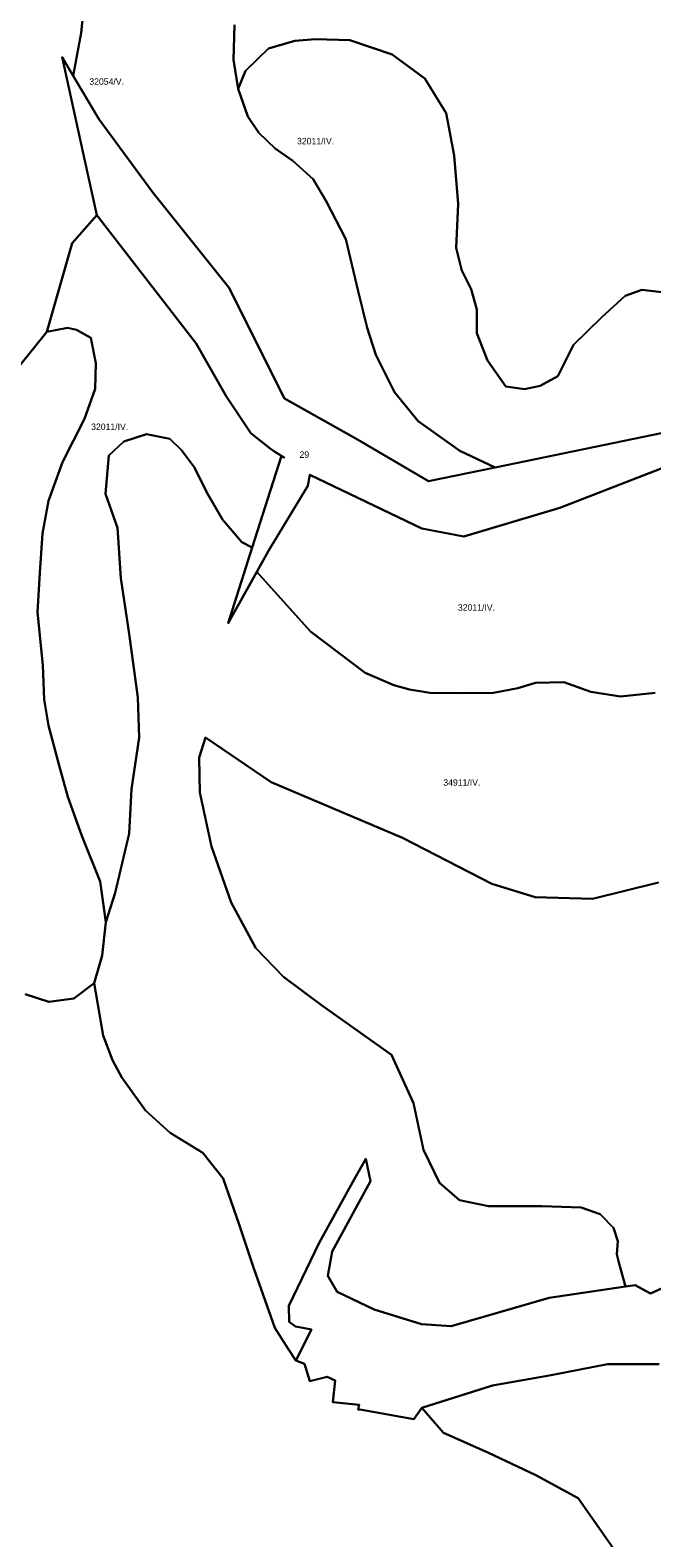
# Model space of a CAD drawing. Extents: x -521621 to -516761, y -1190184 to -1184927.
# Drawn here: x -518790 to -518405, y -1186934 to -1186003 of the extents above; entities that cross this region are included whole.
import ezdxf

# ---------------------------------------------------------------- set-up
doc = ezdxf.new("R2010")
doc.units = 0
doc.layers.add('BPEJ_s', color=7, linetype='Continuous')

msp = doc.modelspace()

# ---------------------------------------------------------------- linework, layer by layer
at = {"layer": 'BPEJ_s'}
for points in [[(-518755.34, -1185978.17), (-518758.01, -1186004.22), (-518762.89, -1186030.84), (-518769.77, -1186019.26), (-518758.59, -1186070.21), (-518748.37, -1186116.79), (-518763.55, -1186134.17), (-518779.14, -1186188.98), (-518803.71, -1186219.42)], [(-518663.33, -1185999.19), (-518663.92, -1186020.8), (-518660.96, -1186038.86), (-518655.06, -1186055.93), (-518648.33, -1186066.04), (-518638.23, -1186075.72), (-518627.28, -1186083.3), (-518614.66, -1186094.67), (-518606.66, -1186108.15), (-518594.46, -1186131.73), (-518586.88, -1186163.74), (-518581.41, -1186186.48), (-518576.05, -1186203.16), (-518564.51, -1186226.26), (-518549.71, -1186244.02), (-518523.97, -1186262.37), (-518502.28, -1186272.68), (-518543.48, -1186281.2), (-518587.23, -1186255.36), (-518632.34, -1186230.07), (-518666.87, -1186161.64), (-518713.8, -1186102.84), (-518746.89, -1186057.79), (-518762.89, -1186030.84), (-518758.01, -1186004.22), (-518755.34, -1185978.17)], [(-518390.45, -1186165.48), (-518411.54, -1186162.94), (-518421.91, -1186166.68), (-518436.64, -1186180.16), (-518453.89, -1186197), (-518463.57, -1186216.37), (-518474.51, -1186222.27), (-518484.19, -1186224.37), (-518495.56, -1186222.69), (-518506.92, -1186206.69), (-518513.65, -1186189.84), (-518513.65, -1186175.1), (-518517.02, -1186162.47), (-518522.91, -1186151.1), (-518526.28, -1186137.21), (-518525.02, -1186109.83), (-518527.54, -1186079.93), (-518532.59, -1186053.82), (-518545.64, -1186032.35), (-518565.84, -1186017.61), (-518591.93, -1186008.77), (-518613.33, -1186008.07), (-518626.05, -1186009.25), (-518642.32, -1186013.99), (-518656.52, -1186027.61), (-518660.96, -1186038.86), (-518663.92, -1186020.8), (-518663.33, -1185999.19)], [(-518398.58, -1186251.24), (-518502.28, -1186272.68), (-518523.97, -1186262.37), (-518549.71, -1186244.02), (-518564.51, -1186226.26), (-518576.05, -1186203.16), (-518581.41, -1186186.48), (-518586.88, -1186163.74), (-518594.46, -1186131.73), (-518606.66, -1186108.15), (-518614.66, -1186094.67), (-518627.28, -1186083.3), (-518638.23, -1186075.72), (-518648.33, -1186066.04), (-518655.06, -1186055.93), (-518660.96, -1186038.86), (-518656.52, -1186027.61), (-518642.32, -1186013.99), (-518626.05, -1186009.25), (-518613.33, -1186008.07), (-518591.93, -1186008.77), (-518565.84, -1186017.61), (-518545.64, -1186032.35), (-518532.59, -1186053.82), (-518527.54, -1186079.93), (-518525.02, -1186109.83), (-518526.28, -1186137.21), (-518522.91, -1186151.1), (-518517.02, -1186162.47), (-518513.65, -1186175.1), (-518513.65, -1186189.84), (-518506.92, -1186206.69), (-518495.56, -1186222.69), (-518484.19, -1186224.37), (-518474.51, -1186222.27), (-518463.57, -1186216.37), (-518453.89, -1186197), (-518436.64, -1186180.16), (-518421.91, -1186166.68), (-518411.54, -1186162.94), (-518390.45, -1186165.48)], [(-518373.06, -1186263.06), (-518462.29, -1186297.62), (-518521.64, -1186315.37), (-518547.55, -1186310.37), (-518616.73, -1186277.29), (-518618.04, -1186284.1), (-518642.2, -1186324.24), (-518649.43, -1186337.23), (-518667.13, -1186369), (-518652.28, -1186322.17), (-518634.49, -1186266.09), (-518632.69, -1186266.61), (-518638.34, -1186263), (-518641.17, -1186260.95), (-518653.25, -1186251.43), (-518668.53, -1186228.68), (-518686.91, -1186196.11), (-518748.37, -1186116.79), (-518758.59, -1186070.21), (-518769.77, -1186019.26), (-518762.89, -1186030.84), (-518746.89, -1186057.79), (-518713.8, -1186102.84), (-518666.87, -1186161.64), (-518632.34, -1186230.07), (-518587.23, -1186255.36), (-518543.48, -1186281.2), (-518502.28, -1186272.68), (-518398.58, -1186251.24)], [(-518803.71, -1186219.42), (-518779.14, -1186188.98), (-518766.43, -1186186.47), (-518760.84, -1186187.71), (-518752.15, -1186192.68), (-518748.95, -1186208.37), (-518749.28, -1186224.04), (-518755.95, -1186242.72), (-518769.61, -1186269.4), (-518778.28, -1186293.41), (-518781.94, -1186313.42), (-518783.61, -1186337.76), (-518784.94, -1186362.11), (-518781.61, -1186394.79), (-518780.94, -1186416.14), (-518778.28, -1186432.14), (-518771.61, -1186456.82), (-518766.28, -1186476.17), (-518757.6, -1186500.24), (-518746.34, -1186528.56), (-518742.69, -1186553.54), (-518745.12, -1186574.25), (-518749.99, -1186591.3), (-518762.47, -1186600.74), (-518778, -1186602.88), (-518792.61, -1186598)], [(-518401.39, -1186529.05), (-518442.01, -1186539.22), (-518477.56, -1186538.26), (-518504.22, -1186530.01), (-518559.44, -1186501.43), (-518640.68, -1186467.13), (-518681.31, -1186439.5), (-518685.12, -1186451.89), (-518684.8, -1186473.48), (-518677.5, -1186506.82), (-518665.44, -1186541.44), (-518650.2, -1186569.7), (-518633.07, -1186587.49), (-518609.61, -1186604.89), (-518566.31, -1186635.58), (-518552.78, -1186665.36), (-518546.47, -1186694.24), (-518536.54, -1186714.55), (-518524.37, -1186725.38), (-518506.33, -1186728.99), (-518473.4, -1186728.99), (-518449.05, -1186729.9), (-518437.32, -1186733.96), (-518429.2, -1186742.53), (-518426.5, -1186750.66), (-518427.02, -1186758.62), (-518425.83, -1186763.8), (-518421.78, -1186778.73), (-518468.84, -1186785.74), (-518498.81, -1186794.43), (-518529.34, -1186803.13), (-518547.69, -1186802.01), (-518576.96, -1186792.89), (-518599.8, -1186782.01), (-518605.57, -1186772.17), (-518603.01, -1186756.98), (-518579.29, -1186713.55), (-518582.06, -1186699.86), (-518589.12, -1186712.27), (-518610.91, -1186751.63), (-518629.72, -1186790.56), (-518629.47, -1186800.57), (-518625.56, -1186803.41), (-518620.98, -1186804.32), (-518615.73, -1186805.32), (-518625.42, -1186824.4), (-518630.19, -1186817.27), (-518638.37, -1186804.29), (-518651.63, -1186767.02), (-518660.38, -1186740.48), (-518670.25, -1186711.96), (-518682.95, -1186696.15), (-518702.98, -1186683.73), (-518718.22, -1186669.9), (-518732.89, -1186649.57), (-518738.73, -1186638.81), (-518744.51, -1186623.59), (-518749.99, -1186591.3), (-518745.12, -1186574.25), (-518742.69, -1186553.54), (-518736.95, -1186535.53), (-518728.28, -1186498.84), (-518726.95, -1186471.5), (-518722.28, -1186439.48), (-518722.95, -1186414.8), (-518728.28, -1186375.45), (-518733.62, -1186341.1), (-518735.62, -1186310.08), (-518742.95, -1186289.07), (-518740.95, -1186265.4), (-518731.62, -1186256.73), (-518717.62, -1186252.06), (-518703.29, -1186255.06), (-518695.95, -1186262.06), (-518687.96, -1186272.73), (-518680.29, -1186288.27), (-518670.73, -1186304.88), (-518658.79, -1186318.79), (-518652.28, -1186322.17), (-518667.13, -1186369), (-518649.43, -1186337.23), (-518616.27, -1186374.14), (-518582.58, -1186399.67), (-518564.92, -1186407.2), (-518555.21, -1186409.96), (-518542.56, -1186411.92), (-518524.29, -1186412.21), (-518503.2, -1186411.92), (-518488.3, -1186409.11), (-518477.33, -1186405.74), (-518459.9, -1186405.45), (-518443.03, -1186411.36), (-518424.75, -1186414.18), (-518403.38, -1186411.93)], [(-518403.38, -1186411.93), (-518424.75, -1186414.18), (-518443.03, -1186411.36), (-518459.9, -1186405.45), (-518477.33, -1186405.74), (-518488.3, -1186409.11), (-518503.2, -1186411.92), (-518524.29, -1186412.21), (-518542.56, -1186411.92), (-518555.21, -1186409.96), (-518564.92, -1186407.2), (-518582.58, -1186399.67), (-518616.27, -1186374.14), (-518649.43, -1186337.23), (-518642.2, -1186324.24), (-518618.04, -1186284.1), (-518616.73, -1186277.29), (-518547.55, -1186310.37), (-518521.64, -1186315.37), (-518462.29, -1186297.62), (-518373.06, -1186263.06)], [(-518381.71, -1186771.88), (-518406.33, -1186783.1), (-518415.68, -1186777.9), (-518421.78, -1186778.73), (-518425.83, -1186763.8), (-518427.02, -1186758.62), (-518426.5, -1186750.66), (-518429.2, -1186742.53), (-518437.32, -1186733.96), (-518449.05, -1186729.9), (-518473.4, -1186728.99), (-518506.33, -1186728.99), (-518524.37, -1186725.38), (-518536.54, -1186714.55), (-518546.47, -1186694.24), (-518552.78, -1186665.36), (-518566.31, -1186635.58), (-518609.61, -1186604.89), (-518633.07, -1186587.49), (-518650.2, -1186569.7), (-518665.44, -1186541.44), (-518677.5, -1186506.82), (-518684.8, -1186473.48), (-518685.12, -1186451.89), (-518681.31, -1186439.5), (-518640.68, -1186467.13), (-518559.44, -1186501.43), (-518504.22, -1186530.01), (-518477.56, -1186538.26), (-518442.01, -1186539.22), (-518401.39, -1186529.05)], [(-518792.61, -1186598), (-518778, -1186602.88), (-518762.47, -1186600.74), (-518749.99, -1186591.3), (-518744.51, -1186623.59), (-518738.73, -1186638.81), (-518732.89, -1186649.57), (-518718.22, -1186669.9), (-518702.98, -1186683.73), (-518682.95, -1186696.15), (-518670.25, -1186711.96), (-518660.38, -1186740.48), (-518651.63, -1186767.02), (-518638.37, -1186804.29), (-518630.19, -1186817.27), (-518625.42, -1186824.4), (-518620.06, -1186826.43), (-518616.73, -1186837.25), (-518606.01, -1186834.51), (-518601.12, -1186836.85), (-518601.71, -1186842.53), (-518602.52, -1186850.05), (-518586.36, -1186851.87), (-518586.88, -1186854.75), (-518584.71, -1186854.82), (-518552.44, -1186860.72), (-518547.6, -1186853.6), (-518534.23, -1186869.07), (-518506.69, -1186881.17), (-518477.12, -1186895.29), (-518450.92, -1186909.41), (-518429.42, -1186940.33)], [(-518400.97, -1186826.76), (-518432.75, -1186826.64), (-518467.55, -1186833.37), (-518503.82, -1186839.81), (-518547.6, -1186853.6), (-518552.44, -1186860.72), (-518584.71, -1186854.82), (-518586.88, -1186854.75), (-518586.36, -1186851.87), (-518602.52, -1186850.05), (-518601.71, -1186842.53), (-518601.12, -1186836.85), (-518606.01, -1186834.51), (-518616.73, -1186837.25), (-518620.06, -1186826.43), (-518625.42, -1186824.4), (-518615.73, -1186805.32), (-518620.98, -1186804.32), (-518625.56, -1186803.41), (-518629.47, -1186800.57), (-518629.72, -1186790.56), (-518610.91, -1186751.63), (-518589.12, -1186712.27), (-518582.06, -1186699.86), (-518579.29, -1186713.55), (-518603.01, -1186756.98), (-518605.57, -1186772.17), (-518599.8, -1186782.01), (-518576.96, -1186792.89), (-518547.69, -1186802.01), (-518529.34, -1186803.13), (-518498.81, -1186794.43), (-518468.84, -1186785.74), (-518421.78, -1186778.73), (-518415.68, -1186777.9), (-518406.33, -1186783.1), (-518381.71, -1186771.88)], [(-518429.42, -1186940.33), (-518450.92, -1186909.41), (-518477.12, -1186895.29), (-518506.69, -1186881.17), (-518534.23, -1186869.07), (-518547.6, -1186853.6), (-518503.82, -1186839.81), (-518467.55, -1186833.37), (-518432.75, -1186826.64), (-518400.97, -1186826.76)]]:
    msp.add_lwpolyline(points, dxfattribs=at)
msp.add_lwpolyline([(-518779.14, -1186188.98), (-518763.55, -1186134.17), (-518748.37, -1186116.79), (-518686.91, -1186196.11), (-518668.53, -1186228.68), (-518653.25, -1186251.43), (-518641.17, -1186260.95), (-518638.34, -1186263), (-518632.69, -1186266.61), (-518634.49, -1186266.09), (-518652.28, -1186322.17), (-518658.79, -1186318.79), (-518670.73, -1186304.88), (-518680.29, -1186288.27), (-518687.96, -1186272.73), (-518695.95, -1186262.06), (-518703.29, -1186255.06), (-518717.62, -1186252.06), (-518731.62, -1186256.73), (-518740.95, -1186265.4), (-518742.95, -1186289.07), (-518735.62, -1186310.08), (-518733.62, -1186341.1), (-518728.28, -1186375.45), (-518722.95, -1186414.8), (-518722.28, -1186439.48), (-518726.95, -1186471.5), (-518728.28, -1186498.84), (-518736.95, -1186535.53), (-518742.69, -1186553.54), (-518746.34, -1186528.56), (-518757.6, -1186500.24), (-518766.28, -1186476.17), (-518771.61, -1186456.82), (-518778.28, -1186432.14), (-518780.94, -1186416.14), (-518781.61, -1186394.79), (-518784.94, -1186362.11), (-518783.61, -1186337.76), (-518781.94, -1186313.42), (-518778.28, -1186293.41), (-518769.61, -1186269.4), (-518755.95, -1186242.72), (-518749.28, -1186224.04), (-518748.95, -1186208.37), (-518752.15, -1186192.68), (-518760.84, -1186187.71), (-518766.43, -1186186.47)], close=True, dxfattribs=at)

# ---------------------------------------------------------------- texts
for s, p in [('32054/V.', (-518752.99, -1186036.32)), ('32011/IV.', (-518624.63, -1186073.1)), ('32011/IV.', (-518751.86, -1186249.58)), ('29', (-518623.12, -1186266.78)), ('32011/IV.', (-518525.25, -1186361.24)), ('34911/IV.', (-518534.26, -1186469.34))]:
    msp.add_text(s, height=4, dxfattribs=at).set_placement(p)

doc.saveas('drawing.dxf')
